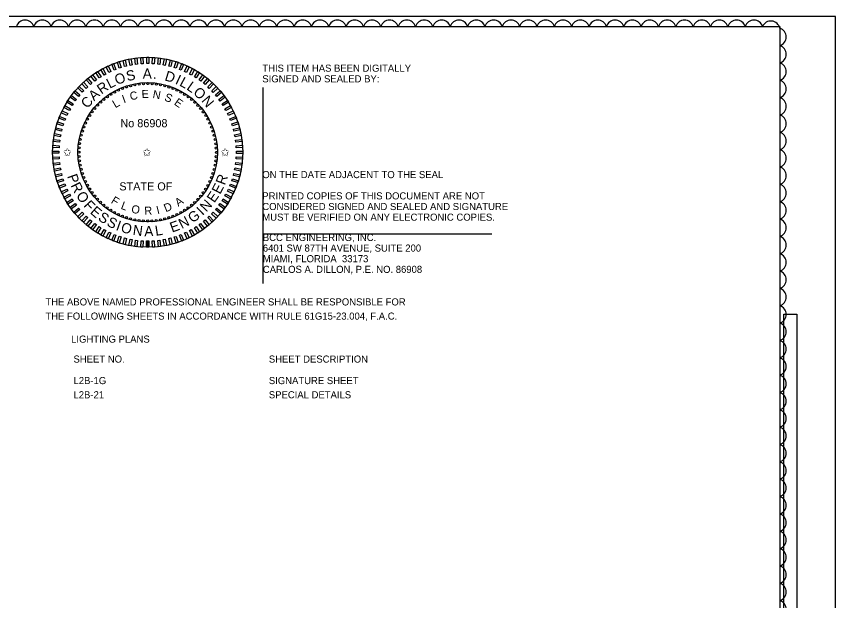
# Model space of a CAD drawing. Extents: x -816.9 to -790.1, y -2199.5 to -2188.9.
# Drawn here: x -802.91 to -794.84, y -2194.66 to -2188.9 of the extents above; entities that cross this region are included whole.
import ezdxf

# ---------------------------------------------------------------- set-up
doc = ezdxf.new("R2010")
doc.units = 0
for name, color, linetype in [('Cloud_dp', 7, 'Continuous'), ('Logo_dp', 7, 'Continuous'), ('NonPlottingEle_dp', 7, 'Continuous'), ('PlotBorder_dp', 7, 'Continuous'), ('ScratchEle_dp', 7, 'Continuous'), ('SheetBorder_dp', 7, 'Continuous'), ('TextMisc', 7, 'Continuous'), ('TextNotes', 7, 'Continuous')]:
    doc.layers.add(name, color=color, linetype=linetype)

msp = doc.modelspace()

# ---------------------------------------------------------------- linework, layer by layer
at = {"layer": 'Cloud_dp'}
for centre, radius, start, end in [((-802.8286, -2189.0276), 0.0897, 17.5, 162.5), ((-802.6575, -2189.0276), 0.0897, 17.5, 162.5), ((-802.4863, -2189.0276), 0.0897, 17.5, 162.5), ((-802.3152, -2189.0276), 0.0897, 17.5, 162.5), ((-802.1441, -2189.0276), 0.0897, 17.5, 162.5), ((-801.973, -2189.0276), 0.0897, 17.5, 162.5), ((-801.8018, -2189.0276), 0.0897, 17.5, 162.5), ((-801.6307, -2189.0276), 0.0897, 17.5, 162.5), ((-801.4596, -2189.0276), 0.0897, 17.5, 162.5), ((-801.2885, -2189.0276), 0.0897, 17.5, 162.5), ((-801.1174, -2189.0276), 0.0897, 17.5, 162.5), ((-800.9462, -2189.0276), 0.0897, 17.5, 162.5), ((-800.7751, -2189.0276), 0.0897, 17.5, 162.5), ((-800.604, -2189.0276), 0.0897, 17.5, 162.5), ((-800.4329, -2189.0276), 0.0897, 17.5, 162.5), ((-800.2617, -2189.0276), 0.0897, 17.5, 162.5), ((-800.0906, -2189.0276), 0.0897, 17.5, 162.5), ((-799.9195, -2189.0276), 0.0897, 17.5, 162.5), ((-799.7484, -2189.0276), 0.0897, 17.5, 162.5), ((-799.5772, -2189.0276), 0.0897, 17.5, 162.5), ((-799.4061, -2189.0276), 0.0897, 17.5, 162.5), ((-799.235, -2189.0276), 0.0897, 17.5, 162.5), ((-799.0639, -2189.0276), 0.0897, 17.5, 162.5), ((-798.8928, -2189.0276), 0.0897, 17.5, 162.5), ((-798.7216, -2189.0276), 0.0897, 17.5, 162.5), ((-798.5505, -2189.0276), 0.0897, 17.5, 162.5), ((-798.3794, -2189.0276), 0.0897, 17.5, 162.5), ((-798.2083, -2189.0276), 0.0897, 17.5, 162.5), ((-798.0371, -2189.0276), 0.0897, 17.5, 162.5), ((-797.866, -2189.0276), 0.0897, 17.5, 162.5), ((-797.6949, -2189.0276), 0.0897, 17.5, 162.5), ((-797.5238, -2189.0276), 0.0897, 17.5, 162.5), ((-797.3527, -2189.0276), 0.0897, 17.5, 162.5), ((-797.1815, -2189.0276), 0.0897, 17.5, 162.5), ((-797.0104, -2189.0276), 0.0897, 17.5, 162.5), ((-796.8393, -2189.0276), 0.0897, 17.5, 162.5), ((-796.6682, -2189.0276), 0.0897, 17.5, 162.5), ((-796.497, -2189.0276), 0.0897, 17.5, 162.5), ((-796.3259, -2189.0276), 0.0897, 17.5, 162.5), ((-796.1548, -2189.0276), 0.0897, 17.5, 162.5), ((-795.9837, -2189.0276), 0.0897, 17.5, 162.5), ((-795.8126, -2189.0276), 0.0897, 17.5, 162.5), ((-795.6414, -2189.0276), 0.0897, 17.5, 162.5), ((-795.4735, -2189.036), 0.0896, 11.74536, 156.74536), ((-795.4127, -2189.1033), 0.0897, 287.5, 72.5), ((-795.4127, -2189.2745), 0.0897, 287.5, 72.5), ((-795.4127, -2189.4456), 0.0897, 287.5, 72.5), ((-795.4127, -2189.6167), 0.0897, 287.5, 72.5), ((-795.4127, -2189.7878), 0.0897, 287.5, 72.5), ((-795.4127, -2189.959), 0.0897, 287.5, 72.5), ((-795.4127, -2190.1301), 0.0897, 287.5, 72.5), ((-795.4127, -2190.3012), 0.0897, 287.5, 72.5), ((-795.4127, -2190.4723), 0.0897, 287.5, 72.5), ((-795.4127, -2190.6434), 0.0897, 287.5, 72.5), ((-795.4127, -2190.8146), 0.0897, 287.5, 72.5), ((-795.4127, -2190.9857), 0.0897, 287.5, 72.5), ((-795.4127, -2191.1568), 0.0897, 287.5, 72.5), ((-795.4127, -2191.3279), 0.0897, 287.5, 72.5), ((-795.4127, -2191.4991), 0.0897, 287.5, 72.5), ((-795.4127, -2191.6702), 0.0897, 287.5, 72.5), ((-795.4127, -2191.8413), 0.0897, 287.5, 72.5), ((-795.4127, -2192.0124), 0.0897, 287.5, 72.5), ((-795.4127, -2192.1835), 0.0897, 287.5, 72.5), ((-795.4127, -2192.3547), 0.0897, 287.5, 72.5), ((-795.4127, -2192.5258), 0.0897, 287.5, 72.5), ((-795.4127, -2192.6969), 0.0897, 287.5, 72.5), ((-795.4127, -2192.868), 0.0897, 287.5, 72.5), ((-795.4127, -2193.0392), 0.0897, 287.5, 72.5), ((-795.4127, -2193.2103), 0.0897, 287.5, 72.5), ((-795.4127, -2193.3814), 0.0897, 287.5, 72.5), ((-795.4127, -2193.5525), 0.0897, 287.5, 72.5), ((-795.4127, -2193.7237), 0.0897, 287.5, 72.5), ((-795.4127, -2193.8948), 0.0897, 287.5, 72.5), ((-795.4127, -2194.0659), 0.0897, 287.5, 72.5), ((-795.4127, -2194.237), 0.0897, 287.5, 72.5), ((-795.4127, -2194.4081), 0.0897, 287.5, 72.5), ((-795.4127, -2194.5793), 0.0897, 287.5, 72.5), ((-795.4127, -2194.7504), 0.0897, 287.5, 72.5)]:
    msp.add_arc(centre, radius, start, end, dxfattribs=at)
at = {"layer": 'Logo_dp'}
for p, q in [((-801.6294, -2191.1792), (-801.6296, -2191.1167)), ((-801.6194, -2191.1792), (-801.6196, -2191.1167)), ((-801.6094, -2191.1792), (-801.6096, -2191.1167))]:
    msp.add_line(p, q, dxfattribs=at)
for points in [[(-801.719, -2189.3723), (-801.739, -2189.3748), (-801.7468, -2189.3129), (-801.7268, -2189.3103)], [(-801.6642, -2189.3677), (-801.6843, -2189.369), (-801.6883, -2189.3067), (-801.6681, -2189.3054)], [(-801.6092, -2189.3667), (-801.6294, -2189.3667), (-801.6294, -2189.3042), (-801.6092, -2189.3042)], [(-801.5543, -2189.369), (-801.5744, -2189.3678), (-801.5705, -2189.3054), (-801.5504, -2189.3067)], [(-801.4996, -2189.3748), (-801.5197, -2189.3723), (-801.5118, -2189.3104), (-801.4918, -2189.3129)], [(-801.9828, -2189.4456), (-802.001, -2189.4542), (-802.0276, -2189.3977), (-802.0094, -2189.3891)], [(-801.9321, -2189.4244), (-801.9508, -2189.4318), (-801.9738, -2189.3737), (-801.955, -2189.3663)], [(-801.8801, -2189.4063), (-801.8993, -2189.4126), (-801.9186, -2189.3532), (-801.8994, -2189.3469)], [(-801.8272, -2189.3916), (-801.8467, -2189.3966), (-801.8622, -2189.3362), (-801.8427, -2189.3311)], [(-801.7734, -2189.3802), (-801.7932, -2189.384), (-801.8049, -2189.3227), (-801.7851, -2189.3189)], [(-801.4454, -2189.3841), (-801.4653, -2189.3803), (-801.4536, -2189.3189), (-801.4337, -2189.3227)], [(-801.3919, -2189.3967), (-801.4115, -2189.3917), (-801.396, -2189.3312), (-801.3764, -2189.3362)], [(-801.3393, -2189.4126), (-801.3585, -2189.4064), (-801.3392, -2189.347), (-801.32, -2189.3532)], [(-801.2878, -2189.4319), (-801.3066, -2189.4244), (-801.2836, -2189.3664), (-801.2648, -2189.3738)], [(-801.2376, -2189.4543), (-801.2559, -2189.4457), (-801.2293, -2189.3892), (-801.211, -2189.3978)], [(-802.1255, -2189.5278), (-802.1418, -2189.5396), (-802.1785, -2189.4891), (-802.1622, -2189.4773)], [(-802.0797, -2189.4974), (-802.0967, -2189.5082), (-802.1302, -2189.4555), (-802.1131, -2189.4447)], [(-802.032, -2189.47), (-802.0497, -2189.4797), (-802.0798, -2189.425), (-802.0621, -2189.4153)], [(-801.1889, -2189.4798), (-801.2066, -2189.4701), (-801.1765, -2189.4154), (-801.1589, -2189.4251)], [(-801.1419, -2189.5083), (-801.159, -2189.4975), (-801.1255, -2189.4448), (-801.1085, -2189.4556)], [(-801.0968, -2189.5398), (-801.1132, -2189.5279), (-801.0765, -2189.4774), (-801.0601, -2189.4892)], [(-802.211, -2189.5968), (-802.2257, -2189.6107), (-802.2684, -2189.5651), (-802.2537, -2189.5513)], [(-802.1693, -2189.561), (-802.1849, -2189.5738), (-802.2247, -2189.5257), (-802.2091, -2189.5129)], [(-801.0538, -2189.574), (-801.0694, -2189.5611), (-801.0296, -2189.513), (-801.014, -2189.5258)], [(-801.013, -2189.6108), (-801.0277, -2189.597), (-800.985, -2189.5515), (-800.9702, -2189.5653)], [(-802.2871, -2189.6761), (-802.3, -2189.6916), (-802.3481, -2189.6518), (-802.3353, -2189.6363)], [(-802.2503, -2189.6353), (-802.2641, -2189.65), (-802.3096, -2189.6072), (-802.2958, -2189.5925)], [(-800.9746, -2189.6501), (-800.9884, -2189.6354), (-800.9429, -2189.5927), (-800.9291, -2189.6074)], [(-800.9387, -2189.6918), (-800.9516, -2189.6762), (-800.9035, -2189.6364), (-800.8906, -2189.652)], [(-802.3213, -2189.7191), (-802.3332, -2189.7354), (-802.3837, -2189.6987), (-802.3719, -2189.6824)], [(-800.9055, -2189.7356), (-800.9174, -2189.7193), (-800.8669, -2189.6826), (-800.855, -2189.6989)], [(-802.3813, -2189.8112), (-802.391, -2189.8289), (-802.4457, -2189.7988), (-802.436, -2189.7811)], [(-802.3528, -2189.7642), (-802.3636, -2189.7813), (-802.4163, -2189.7478), (-802.4055, -2189.7308)], [(-800.8751, -2189.7814), (-800.886, -2189.7644), (-800.8332, -2189.7309), (-800.8224, -2189.748)], [(-800.8477, -2189.8291), (-800.8574, -2189.8114), (-800.8027, -2189.7813), (-800.793, -2189.799)], [(-802.4068, -2189.8599), (-802.4154, -2189.8782), (-802.4719, -2189.8516), (-802.4633, -2189.8333)], [(-800.8233, -2189.8783), (-800.8319, -2189.8601), (-800.7754, -2189.8335), (-800.7668, -2189.8517)], [(-802.4485, -2189.9616), (-802.4547, -2189.9808), (-802.5141, -2189.9615), (-802.5079, -2189.9423)], [(-802.4292, -2189.9101), (-802.4367, -2189.9289), (-802.4947, -2189.9059), (-802.4873, -2189.8871)], [(-800.8021, -2189.929), (-800.8095, -2189.9103), (-800.7515, -2189.8873), (-800.744, -2189.906)], [(-800.7841, -2189.981), (-800.7903, -2189.9618), (-800.7309, -2189.9425), (-800.7247, -2189.9617)], [(-802.4644, -2190.0142), (-802.4694, -2190.0338), (-802.5299, -2190.0182), (-802.5249, -2189.9987)], [(-800.7693, -2190.0339), (-800.7744, -2190.0144), (-800.7139, -2189.9989), (-800.7089, -2190.0184)], [(-802.4863, -2190.1219), (-802.4888, -2190.1419), (-802.5507, -2190.1341), (-802.5482, -2190.1141)], [(-802.477, -2190.0677), (-802.4808, -2190.0875), (-802.5422, -2190.0758), (-802.5384, -2190.056)], [(-800.758, -2190.0877), (-800.7618, -2190.0679), (-800.7004, -2190.0562), (-800.6966, -2190.076)], [(-800.75, -2190.1421), (-800.7525, -2190.1221), (-800.6906, -2190.1143), (-800.6881, -2190.1343)], [(-802.4921, -2190.1766), (-802.4933, -2190.1967), (-802.5557, -2190.1928), (-802.5544, -2190.1727)], [(-800.7455, -2190.1969), (-800.7467, -2190.1768), (-800.6844, -2190.1728), (-800.6832, -2190.193)], [(-802.4944, -2190.2315), (-802.4944, -2190.2517), (-802.5569, -2190.2517), (-802.5569, -2190.2315)], [(-802.4934, -2190.2865), (-802.4921, -2190.3066), (-802.5544, -2190.3105), (-802.5557, -2190.2904)], [(-800.7467, -2190.3068), (-800.7455, -2190.2866), (-800.6832, -2190.2906), (-800.6844, -2190.3107)], [(-800.7444, -2190.2519), (-800.7444, -2190.2317), (-800.6819, -2190.2317), (-800.6819, -2190.2519)], [(-802.4888, -2190.3412), (-802.4863, -2190.3613), (-802.5482, -2190.3691), (-802.5508, -2190.3491)], [(-800.7526, -2190.3615), (-800.75, -2190.3414), (-800.6881, -2190.3493), (-800.6906, -2190.3693)], [(-802.4809, -2190.3956), (-802.4771, -2190.4155), (-802.5384, -2190.4272), (-802.5422, -2190.4073)], [(-800.7618, -2190.4157), (-800.758, -2190.3958), (-800.6967, -2190.4075), (-800.7005, -2190.4274)], [(-802.4695, -2190.4494), (-802.4645, -2190.469), (-802.5249, -2190.4845), (-802.53, -2190.465)], [(-802.4548, -2190.5024), (-802.4485, -2190.5216), (-802.5079, -2190.5409), (-802.5141, -2190.5217)], [(-800.7904, -2190.5218), (-800.7841, -2190.5026), (-800.7247, -2190.5219), (-800.731, -2190.5411)], [(-800.7744, -2190.4692), (-800.7694, -2190.4496), (-800.7089, -2190.4651), (-800.7139, -2190.4847)], [(-802.4367, -2190.5543), (-802.4293, -2190.5731), (-802.4874, -2190.5961), (-802.4948, -2190.5773)], [(-802.4155, -2190.605), (-802.4069, -2190.6233), (-802.4634, -2190.6499), (-802.472, -2190.6316)], [(-800.832, -2190.6235), (-800.8234, -2190.6052), (-800.7669, -2190.6318), (-800.7755, -2190.6501)], [(-800.8096, -2190.5733), (-800.8021, -2190.5545), (-800.7441, -2190.5775), (-800.7515, -2190.5963)], [(-802.3911, -2190.6543), (-802.3814, -2190.672), (-802.4361, -2190.7021), (-802.4458, -2190.6844)], [(-800.8575, -2190.6722), (-800.8478, -2190.6545), (-800.7931, -2190.6846), (-800.8028, -2190.7022)], [(-802.3637, -2190.7019), (-802.3529, -2190.719), (-802.4056, -2190.7524), (-802.4164, -2190.7354)], [(-802.3333, -2190.7478), (-802.3214, -2190.7641), (-802.372, -2190.8008), (-802.3838, -2190.7845)], [(-800.9175, -2190.7643), (-800.9056, -2190.7479), (-800.8551, -2190.7846), (-800.867, -2190.801)], [(-800.8861, -2190.7191), (-800.8752, -2190.7021), (-800.8225, -2190.7356), (-800.8333, -2190.7526)], [(-802.3001, -2190.7916), (-802.2873, -2190.8072), (-802.3354, -2190.847), (-802.3482, -2190.8314)], [(-802.2643, -2190.8333), (-802.2504, -2190.848), (-802.296, -2190.8907), (-802.3098, -2190.876)], [(-800.9885, -2190.8481), (-800.9747, -2190.8334), (-800.9292, -2190.8761), (-800.943, -2190.8909)], [(-800.9517, -2190.8073), (-800.9388, -2190.7917), (-800.8907, -2190.8315), (-800.9036, -2190.8471)], [(-802.2258, -2190.8726), (-802.2111, -2190.8864), (-802.2539, -2190.9319), (-802.2686, -2190.9181)], [(-802.185, -2190.9094), (-802.1695, -2190.9223), (-802.2093, -2190.9704), (-802.2248, -2190.9575)], [(-801.0695, -2190.9224), (-801.0539, -2190.9095), (-801.0141, -2190.9576), (-801.0297, -2190.9705)], [(-801.0278, -2190.8865), (-801.0131, -2190.8727), (-800.9704, -2190.9182), (-800.9851, -2190.932)], [(-802.142, -2190.9436), (-802.1257, -2190.9555), (-802.1624, -2191.006), (-802.1787, -2190.9941)], [(-802.0969, -2190.975), (-802.0798, -2190.9859), (-802.1133, -2191.0386), (-802.1303, -2191.0278)], [(-802.0499, -2191.0036), (-802.0322, -2191.0133), (-802.0623, -2191.068), (-802.08, -2191.0583)], [(-801.2068, -2191.0134), (-801.1891, -2191.0037), (-801.159, -2191.0584), (-801.1767, -2191.0681)], [(-801.1591, -2190.986), (-801.1421, -2190.9751), (-801.1086, -2191.0279), (-801.1257, -2191.0387)], [(-801.1133, -2190.9556), (-801.097, -2190.9437), (-801.0603, -2190.9942), (-801.0766, -2191.0061)], [(-802.0012, -2191.0291), (-801.9829, -2191.0377), (-802.0095, -2191.0942), (-802.0278, -2191.0856)], [(-801.951, -2191.0515), (-801.9322, -2191.0589), (-801.9552, -2191.117), (-801.974, -2191.1096)], [(-801.8995, -2191.0707), (-801.8803, -2191.077), (-801.8996, -2191.1364), (-801.9188, -2191.1301)], [(-801.8469, -2191.0867), (-801.8273, -2191.0917), (-801.8429, -2191.1522), (-801.8624, -2191.1472)], [(-801.4117, -2191.0918), (-801.3921, -2191.0867), (-801.3766, -2191.1472), (-801.3961, -2191.1522)], [(-801.3587, -2191.077), (-801.3395, -2191.0708), (-801.3202, -2191.1302), (-801.3394, -2191.1364)], [(-801.3068, -2191.059), (-801.288, -2191.0516), (-801.265, -2191.1096), (-801.2838, -2191.1171)], [(-801.2561, -2191.0378), (-801.2378, -2191.0292), (-801.2112, -2191.0857), (-801.2295, -2191.0943)], [(-801.7934, -2191.0993), (-801.7736, -2191.1031), (-801.7853, -2191.1644), (-801.8051, -2191.1606)], [(-801.7392, -2191.1085), (-801.7192, -2191.1111), (-801.727, -2191.173), (-801.747, -2191.1705)], [(-801.6845, -2191.1143), (-801.6644, -2191.1156), (-801.6683, -2191.1779), (-801.6884, -2191.1767)], [(-801.6296, -2191.1167), (-801.6094, -2191.1167), (-801.6094, -2191.1792), (-801.6296, -2191.1792)], [(-801.5746, -2191.1156), (-801.5545, -2191.1144), (-801.5506, -2191.1767), (-801.5707, -2191.1779)], [(-801.5198, -2191.1111), (-801.4998, -2191.1086), (-801.492, -2191.1705), (-801.512, -2191.173)], [(-801.4655, -2191.1031), (-801.4456, -2191.0993), (-801.4339, -2191.1607), (-801.4538, -2191.1645)]]:
    msp.add_lwpolyline(points, close=True, dxfattribs=at)
for centre in [(-801.7038, -2189.5695), (-801.6614, -2189.5655), (-801.6188, -2189.5642), (-801.5763, -2189.5656), (-801.5339, -2189.5696), (-801.9453, -2189.6477), (-801.9074, -2189.6285), (-801.8683, -2189.6116), (-801.8282, -2189.5972), (-801.7873, -2189.5854), (-801.7458, -2189.5761), (-801.4919, -2189.5763), (-801.4504, -2189.5856), (-801.4095, -2189.5975), (-801.3695, -2189.612), (-801.3305, -2189.6289), (-801.2925, -2189.6483), (-802.0508, -2189.7193), (-802.0172, -2189.6933), (-801.9819, -2189.6694), (-801.2559, -2189.67), (-801.2208, -2189.6939), (-801.1871, -2189.72), (-802.1411, -2189.8094), (-802.1129, -2189.7775), (-802.0828, -2189.7474), (-801.1552, -2189.7482), (-801.1252, -2189.7783), (-801.0971, -2189.8103), (-802.1911, -2189.8782), (-802.1672, -2189.843), (-801.071, -2189.8439), (-801.0471, -2189.8792), (-802.2322, -2189.9527), (-802.2128, -2189.9148), (-801.0255, -2189.9158), (-801.0062, -2189.9537), (-802.2635, -2190.0318), (-802.2491, -2189.9918), (-800.9893, -2189.9928), (-800.9749, -2190.0329), (-802.2848, -2190.1142), (-802.2755, -2190.0727), (-800.9631, -2190.0738), (-800.9538, -2190.1153), (-802.2955, -2190.1986), (-802.2915, -2190.1562), (-800.9472, -2190.1573), (-800.9432, -2190.1997), (-802.2969, -2190.2411), (-802.2956, -2190.2837), (-800.9433, -2190.2848), (-800.9419, -2190.2422), (-802.2916, -2190.326), (-802.285, -2190.3681), (-800.9541, -2190.3692), (-800.9474, -2190.3272), (-802.2757, -2190.4096), (-802.2639, -2190.4505), (-800.9753, -2190.4516), (-800.9634, -2190.4107), (-802.2495, -2190.4906), (-802.2326, -2190.5296), (-801.0067, -2190.5306), (-800.9897, -2190.4916), (-802.2134, -2190.5676), (-802.1917, -2190.6042), (-801.0477, -2190.6052), (-801.026, -2190.5686), (-802.1678, -2190.6394), (-802.1418, -2190.6731), (-801.0978, -2190.674), (-801.0717, -2190.6403), (-802.1137, -2190.705), (-802.0836, -2190.7352), (-802.0517, -2190.7633), (-801.188, -2190.764), (-801.1561, -2190.7359), (-801.1259, -2190.7059), (-802.0181, -2190.7894), (-801.9829, -2190.8134), (-801.9463, -2190.8351), (-801.9084, -2190.8544), (-801.3315, -2190.8549), (-801.2935, -2190.8356), (-801.2569, -2190.814), (-801.2217, -2190.7901), (-801.8693, -2190.8714), (-801.8293, -2190.8858), (-801.7884, -2190.8977), (-801.7469, -2190.907), (-801.7049, -2190.9137), (-801.6625, -2190.9178), (-801.6194, -2190.9192), (-801.5774, -2190.9179), (-801.5351, -2190.9139), (-801.493, -2190.9073), (-801.4515, -2190.898), (-801.4106, -2190.8862), (-801.3705, -2190.8718)]:
    msp.add_circle(centre, 0.01, dxfattribs=at)
at = {"layer": 'NonPlottingEle_dp'}
for radius in [0.9375, 0.6875]:
    msp.add_circle((-801.6194, -2190.2417), radius, dxfattribs=at)
at = {"layer": 'PlotBorder_dp'}
msp.add_lwpolyline([(-811.3358, -2199.5006), (-794.8358, -2199.5006), (-794.8358, -2188.9006), (-811.3358, -2188.9006)], close=True, dxfattribs=at)
at = {"layer": 'ScratchEle_dp'}
for p, q in [((-800.484, -2189.6017), (-800.484, -2191.5365)), ((-800.484, -2191.0465), (-798.2273, -2191.0465))]:
    msp.add_line(p, q, dxfattribs=at)
msp.add_lwpolyline([(-795.3456, -2191.8382), (-795.218, -2191.8382), (-795.218, -2198.6801), (-795.3456, -2198.6801)], close=True, dxfattribs=at)
at = {"layer": 'SheetBorder_dp'}
for p, q in [((-810.7858, -2189.0006), (-795.3858, -2189.0006)), ((-795.3858, -2189.0006), (-795.3858, -2199.4006))]:
    msp.add_line(p, q, dxfattribs=at)

# ---------------------------------------------------------------- texts
at = {"layer": 'Logo_dp'}
for s, height, rotation, p in [('O', 0.1, 20.77943, (-801.9234, -2189.5789)), ('S', 0.1, 12.11857, (-801.8202, -2189.5407)), ('A', 0.1, 359.96678, (-801.6681, -2189.5142)), ('D', 0.1, 343.34565, (-801.458, -2189.5306)), ('I', 0.1, 334.86598, (-801.3549, -2189.5622)), ('R', 0.1, 34.8639, (-802.0756, -2189.6728)), ('L', 0.1, 27.04255, (-801.9939, -2189.6161)), ('.', 0.1, 352.19979, (-801.5693, -2189.5142)), ('L', 0.1, 331.33278, (-801.3135, -2189.5798)), ('L', 0.1, 325.06966, (-801.2431, -2189.6171)), ('A', 0.1, 42.6309, (-802.1483, -2189.7397)), ('C', 0.08, 12.20255, (-801.7871, -2189.7301)), ('E', 0.08, 0.41861, (-801.6791, -2189.7066)), ('N', 0.08, 349.29143, (-801.5747, -2189.7051)), ('O', 0.1, 318.80654, (-801.1772, -2189.6619)), ('C', 0.1, 50.36769, (-802.211, -2189.8155)), ('I', 0.08, 20.01168, (-801.8551, -2189.7576)), ('S', 0.08, 337.02207, (-801.4617, -2189.7269)), ('E', 0.08, 325.86633, (-801.3651, -2189.7671)), ('N', 0.1, 310.14568, (-801.095, -2189.7351)), ('L', 0.08, 30.40215, (-801.9385, -2189.8081)), ('P', 0.1, 289.40551, (-802.4141, -2190.4763)), ('R', 0.1, 69.5134, (-800.8592, -2190.5714)), ('R', 0.1, 296.14576, (-802.3811, -2190.5679)), ('E', 0.1, 62.47116, (-800.9054, -2190.6621)), ('O', 0.1, 303.96711, (-802.3296, -2190.6685)), ('F', 0.08, 328.72408, (-801.9875, -2190.7383)), ('E', 0.1, 55.42892, (-800.9623, -2190.7465)), ('F', 0.1, 312.62798, (-802.2572, -2190.7706)), ('E', 0.1, 319.07833, (-802.1938, -2190.8389)), ('L', 0.08, 339.29159, (-801.8902, -2190.7973)), ('O', 0.08, 349.68206, (-801.7855, -2190.8371)), ('I', 0.08, 14.20366, (-801.5234, -2190.8523)), ('D', 0.08, 22.01279, (-801.4413, -2190.8336)), ('A', 0.08, 34.49917, (-801.3176, -2190.7811)), ('N', 0.1, 47.17876, (-801.0415, -2190.8355)), ('S', 0.1, 326.12056, (-802.1162, -2190.9048)), ('R', 0.08, 2.33977, (-801.651, -2190.859)), ('G', 0.1, 35.11153, (-801.1785, -2190.9432)), ('I', 0.1, 43.64556, (-801.0792, -2190.87)), ('S', 0.1, 333.193, (-802.0308, -2190.961)), ('I', 0.1, 340.26543, (-801.9391, -2191.0061)), ('E', 0.1, 19.81912, (-801.3791, -2191.0347)), ('N', 0.1, 26.86136, (-801.2837, -2190.9992)), ('O', 0.1, 343.79863, (-801.8914, -2191.0244)), ('N', 0.1, 352.45949, (-801.7704, -2191.0564)), ('A', 0.1, 0.70966, (-801.652, -2191.0697)), ('L', 0.1, 8.47665, (-801.5398, -2191.0665))]:
    msp.add_text(s, height=height, rotation=rotation, dxfattribs=at).set_placement(p)
for s, p in [('No 86908', (-801.8884, -2189.9944)), ('✩', (-802.4544, -2190.2796)), ('✩', (-801.6697, -2190.2796)), ('✩', (-800.8978, -2190.2796)), ('STATE OF', (-801.8991, -2190.6179))]:
    msp.add_text(s, height=0.08, dxfattribs=at).set_placement(p)
at = {"layer": 'TextMisc'}
for s, p in [('THIS ITEM HAS BEEN DIGITALLY', (-800.489, -2189.4466)), ('SIGNED AND SEALED BY:', (-800.489, -2189.5516)), ('ON THE DATE ADJACENT TO THE SEAL', (-800.489, -2190.4966)), ('PRINTED COPIES OF THIS DOCUMENT ARE NOT ', (-800.489, -2190.7066)), ('CONSIDERED SIGNED AND SEALED AND SIGNATURE ', (-800.489, -2190.8116)), ('MUST BE VERIFIED ON ANY ELECTRONIC COPIES.', (-800.489, -2190.9166)), ('BCC ENGINEERING, INC.', (-800.484, -2191.1165)), ('6401 SW 87TH AVENUE, SUITE 200', (-800.484, -2191.2215)), ('MIAMI, FLORIDA  33173', (-800.484, -2191.3265)), ('CARLOS A. DILLON, P.E. NO. 86908', (-800.484, -2191.4315)), ('THE ABOVE NAMED PROFESSIONAL ENGINEER SHALL BE RESPONSIBLE FOR ', (-802.6281, -2191.7526)), ('THE FOLLOWING SHEETS IN ACCORDANCE WITH RULE 61G15-23.004, F.A.C.', (-802.6281, -2191.8926)), ('LIGHTING PLANS', (-802.3744, -2192.1196))]:
    msp.add_text(s, height=0.07, dxfattribs=at).set_placement(p)
at = {"layer": 'TextNotes'}
for s, p in [('SHEET NO.', (-802.3509, -2192.3166)), ('SHEET DESCRIPTION', (-800.4246, -2192.3166)), ('L2B-1G', (-802.3509, -2192.5288)), ('SIGNATURE SHEET', (-800.4246, -2192.5288)), ('L2B-21', (-802.3509, -2192.6688)), ('SPECIAL DETAILS', (-800.4246, -2192.6688))]:
    msp.add_text(s, height=0.07, dxfattribs=at).set_placement(p)

doc.saveas('drawing.dxf')
